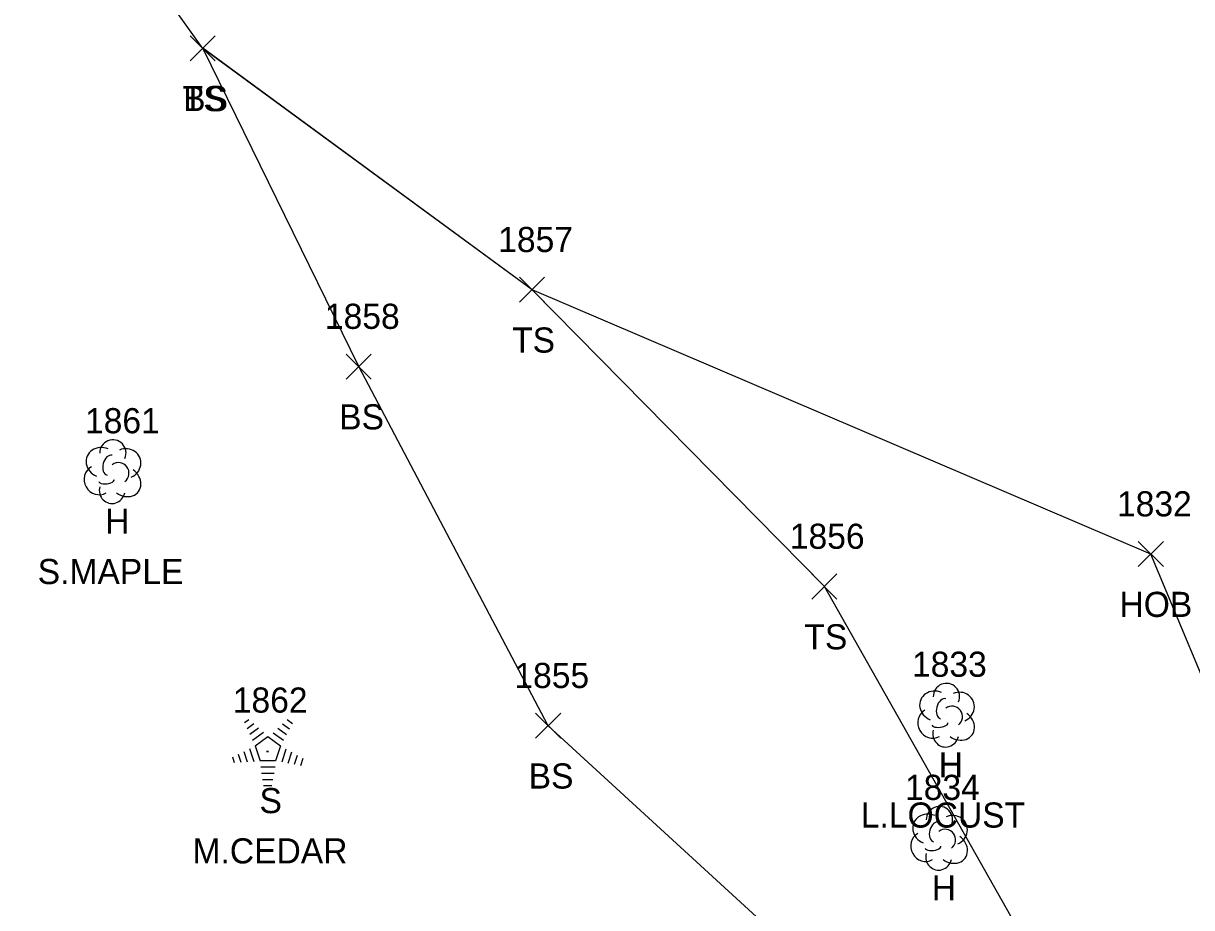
# Model space of a CAD drawing. Extents: x 1443590 to 1445966, y 578314 to 580556.
# Drawn here: x 1445125.4 to 1445218.3, y 579179 to 579249.3 of the extents above; entities that cross this region are included whole.
import ezdxf

# ---------------------------------------------------------------- set-up
doc = ezdxf.new("R2010")
doc.units = 0
for name, color, linetype in [('L_A', 7, 'Continuous'), ('L_C', 7, 'Continuous'), ('L_I', 7, 'Continuous'), ('L_TIC', 7, 'Continuous'), ('LBC', 7, 'Continuous'), ('LELB', 7, 'Continuous'), ('LSOGP', 7, 'Continuous'), ('LTC', 7, 'Continuous'), ('LTD', 7, 'Continuous')]:
    doc.layers.add(name, color=color, linetype=linetype)

msp = doc.modelspace()

# ---------------------------------------------------------------- linework, layer by layer
at = {"layer": 'L_TIC'}
for points in [[(1445138.649, 579246.344), (1445140.649, 579248.344)], [(1445140.649, 579246.344), (1445138.649, 579248.344)], [(1445138.649, 579246.344), (1445140.649, 579248.344)], [(1445140.649, 579246.344), (1445138.649, 579248.344)], [(1445164.858, 579227.133), (1445166.858, 579229.133)], [(1445166.858, 579227.133), (1445164.858, 579229.133)], [(1445151.066, 579221.021), (1445153.066, 579223.021)], [(1445153.066, 579221.021), (1445151.066, 579223.021)], [(1445214.097, 579206.101), (1445216.097, 579208.101)], [(1445216.097, 579206.101), (1445214.097, 579208.101)], [(1445188.117, 579203.521), (1445190.117, 579205.521)], [(1445190.117, 579203.521), (1445188.117, 579205.521)], [(1445166.143, 579192.445), (1445168.143, 579194.445)], [(1445168.143, 579192.445), (1445166.143, 579194.445)]]:
    msp.add_lwpolyline(points, dxfattribs=at)
at = {"layer": 'LBC'}
msp.add_lwpolyline([(1445229.803, 579195.68), (1445221.335, 579192.193), (1445215.097, 579207.101)], dxfattribs=at)
at = {"layer": 'LELB'}
for points in [[(1445211.413, 579150.38), (1445191.373, 579171.209), (1445167.143, 579193.445), (1445152.066, 579222.021), (1445139.649, 579247.344)], [(1445219.964, 579155.852), (1445207.396, 579172.202), (1445189.117, 579204.521), (1445165.858, 579228.133), (1445139.649, 579247.344)]]:
    msp.add_lwpolyline(points, dxfattribs=at)
at = {"layer": 'LSOGP'}
msp.add_lwpolyline([(1445322.239, 579228.805), (1445303.405, 579226.368), (1445294.772, 579223.005), (1445282.438, 579219.832), (1445270.202, 579218.157), (1445258.858, 579215.543), (1445266.05, 579197.405), (1445250.568, 579190.872), (1445246.454, 579189.539), (1445234.26, 579184.757), (1445229.801, 579195.675), (1445221.335, 579192.193), (1445215.096, 579207.096), (1445165.858, 579228.133), (1445139.649, 579247.343), (1445128.368, 579263.152), (1445122.129, 579272.364)], dxfattribs=at)
at = {"layer": 'LTC'}
for p, q in [((1445142.976, 579193.695), (1445143.33, 579193.952)), ((1445146.374, 579193.935), (1445146.793, 579193.631)), ((1445143.185, 579193.23), (1445143.714, 579193.614)), ((1445143.395, 579192.764), (1445144.099, 579193.275)), ((1445145.632, 579193.239), (1445146.311, 579192.745)), ((1445146.003, 579193.587), (1445146.552, 579193.188)), ((1445143.604, 579192.298), (1445144.483, 579192.936)), ((1445143.829, 579191.843), (1445144.841, 579192.577)), ((1445144.841, 579192.577), (1445145.838, 579191.852)), ((1445145.261, 579192.89), (1445146.07, 579192.302)), ((1445142.464, 579191.191), (1445142.675, 579190.539)), ((1445142.919, 579191.407), (1445143.19, 579190.572)), ((1445143.374, 579191.624), (1445143.705, 579190.605)), ((1445143.829, 579191.843), (1445144.216, 579190.65)), ((1445145.838, 579191.852), (1445145.447, 579190.65)), ((1445146.275, 579191.582), (1445145.937, 579190.542)), ((1445146.72, 579191.331), (1445146.432, 579190.447)), ((1445142.008, 579190.974), (1445142.16, 579190.506)), ((1445145.447, 579190.65), (1445144.216, 579190.65)), ((1445147.164, 579191.081), (1445146.927, 579190.352)), ((1445147.609, 579190.831), (1445147.422, 579190.257)), ((1445145.408, 579190.15), (1445144.264, 579190.15)), ((1445145.324, 579189.65), (1445144.336, 579189.65)), ((1445145.241, 579189.15), (1445144.409, 579189.15)), ((1445145.157, 579188.65), (1445144.482, 579188.65))]:
    msp.add_line(p, q, dxfattribs=at)
at = {"layer": 'LTD'}
for p, q in [((1445132.453, 579213.715), (1445132.453, 579213.715)), ((1445132.453, 579213.715), (1445132.453, 579213.715)), ((1445198.785, 579194.338), (1445198.785, 579194.338)), ((1445198.785, 579194.338), (1445198.785, 579194.338)), ((1445198.23, 579184.54), (1445198.23, 579184.54)), ((1445198.23, 579184.54), (1445198.23, 579184.54))]:
    msp.add_line(p, q, dxfattribs=at)
for centre in [(1445132.5, 579215.149), (1445198.831, 579195.772), (1445198.277, 579185.974)]:
    msp.add_arc(centre, 1.047, 335.52715, 180.95627, dxfattribs=at)
for centre, major_axis, ratio, start_param, end_param in [((1445131.661, 579214.382), (1.21, -0.512), 0.895232, 1.570796, 4.712389), ((1445133.495, 579214.299), (-1.141, -0.483), 0.949671, 1.570796, 4.712389), ((1445132.245, 579214.174), (-0.208, -0.792), 0.645439, 3.141593, 6.283185), ((1445132.953, 579213.549), (-0.5, 0.667), 0.989748, 3.141593, 6.283185), ((1445131.37, 579213.007), (0.584, -1.042), 0.959034, 3.141593, 6.283185), ((1445133.453, 579212.882), (-1.09, 0.792), 0.841452, 1.570796, 4.712389), ((1445131.995, 579212.965), (-0.625, -0.083), 0.423636, 0, 3.141593), ((1445132.453, 579212.215), (0.265, 1.061), 0.942809, 1.570796, 4.712389), ((1445197.993, 579195.004), (1.21, -0.512), 0.895232, 1.570796, 4.712389), ((1445199.826, 579194.921), (-1.141, -0.483), 0.949671, 1.570796, 4.712389), ((1445198.576, 579194.796), (-0.208, -0.792), 0.645439, 3.141593, 6.283185), ((1445199.285, 579194.171), (-0.5, 0.667), 0.989748, 3.141593, 6.283185), ((1445197.701, 579193.629), (0.584, -1.042), 0.959034, 3.141593, 6.283185), ((1445199.785, 579193.505), (-1.09, 0.792), 0.841452, 1.570796, 4.712389), ((1445198.785, 579192.838), (0.265, 1.061), 0.942809, 1.570796, 4.712389), ((1445198.326, 579193.588), (-0.625, -0.083), 0.423636, 0, 3.141593), ((1445197.438, 579185.206), (1.21, -0.512), 0.895232, 1.570796, 4.712389), ((1445199.271, 579185.123), (-1.141, -0.483), 0.949671, 1.570796, 4.712389), ((1445198.021, 579184.998), (-0.208, -0.792), 0.645439, 3.141593, 6.283185), ((1445197.147, 579183.831), (0.584, -1.042), 0.959034, 3.141593, 6.283185), ((1445198.73, 579184.373), (-0.5, 0.667), 0.989748, 3.141593, 6.283185), ((1445199.23, 579183.707), (-1.09, 0.792), 0.841452, 1.570796, 4.712389), ((1445197.772, 579183.79), (-0.625, -0.083), 0.423636, 0, 3.141593), ((1445198.23, 579183.04), (0.265, 1.061), 0.942809, 1.570796, 4.712389)]:
    msp.add_ellipse(centre, major_axis=major_axis, ratio=ratio, start_param=start_param, end_param=end_param, dxfattribs=at)

# ---------------------------------------------------------------- texts
at = {"layer": 'L_A'}
for s, p in [('TS', (1445138.058, 579242.344)), ('BS', (1445138.09, 579242.344)), ('TS', (1445164.267, 579223.133)), ('BS', (1445150.507, 579217.021)), ('H', (1445131.886, 579208.715)), ('HOB', (1445212.601, 579202.101)), ('TS', (1445187.527, 579199.521)), ('H', (1445198.218, 579189.338)), ('BS', (1445165.584, 579188.445)), ('S', (1445144.166, 579186.487)), ('H', (1445197.663, 579179.54))]:
    msp.add_text(s, height=2, dxfattribs=at).set_placement(p)
at = {"layer": 'L_C'}
for s, p in [('S.MAPLE', (1445126.516, 579204.715)), ('L.LOCUST', (1445192.021, 579185.338)), ('M.CEDAR', (1445138.836, 579182.487))]:
    msp.add_text(s, height=2, dxfattribs=at).set_placement(p)
at = {"layer": 'L_I'}
for s, p in [('1857', (1445163.165, 579231.133)), ('1858', (1445149.373, 579225.021)), ('1861', (1445130.28, 579216.715)), ('1832', (1445212.404, 579210.101)), ('1856', (1445186.369, 579207.521)), ('1833', (1445196.092, 579197.338)), ('1855', (1445164.45, 579196.445)), ('1862', (1445142.041, 579194.487)), ('1834', (1445195.537, 579187.54))]:
    msp.add_text(s, height=2, dxfattribs=at).set_placement(p)
at = {"layer": 'LTC'}
msp.add_text('.', height=1.037, rotation=270, dxfattribs=at).set_placement((1445144.723, 579191.591))

doc.saveas('drawing.dxf')
